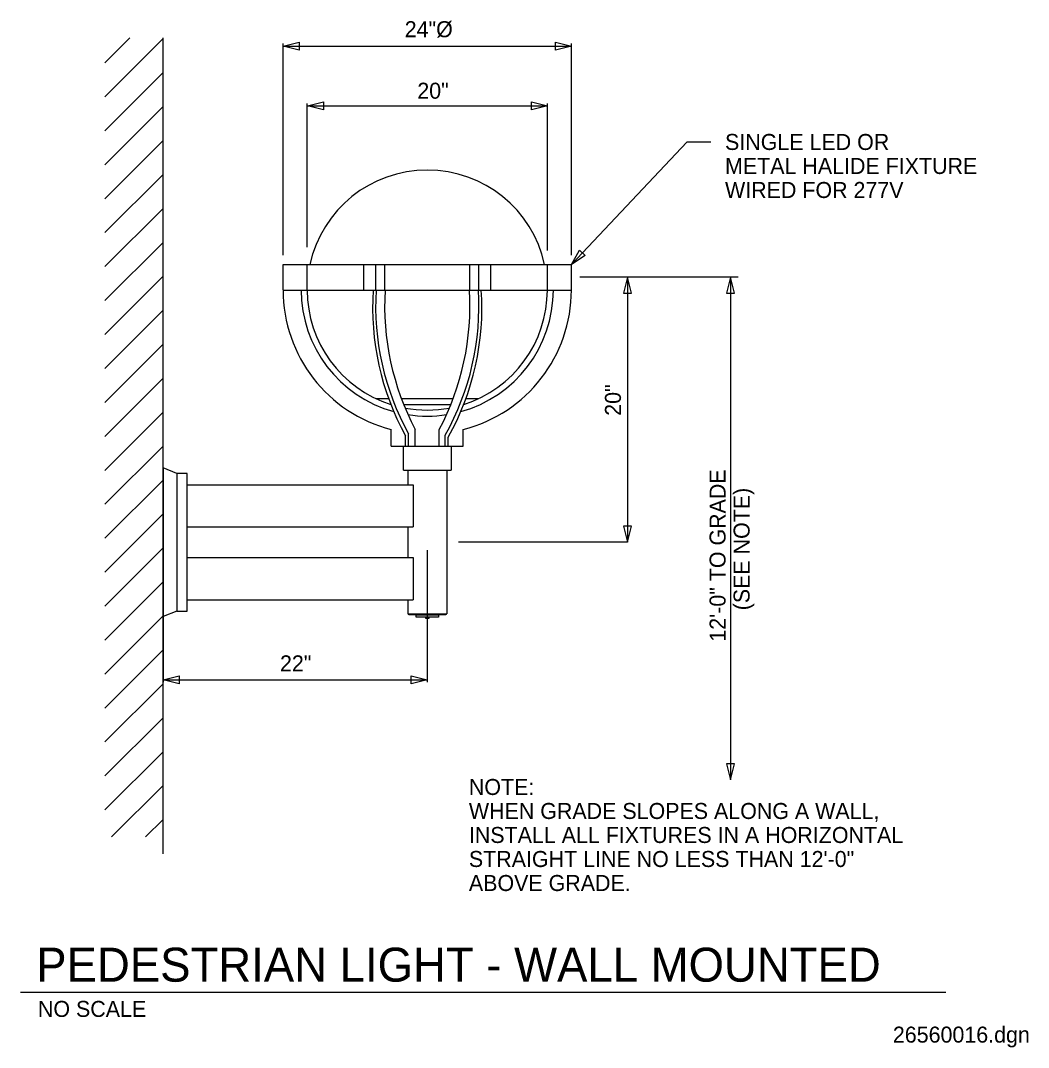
# Model space of a CAD drawing. Extents: x 10115.6 to 10157.6, y 10056 to 10098.8.
import ezdxf

# ---------------------------------------------------------------- set-up
doc = ezdxf.new("R2010")
doc.units = 0
for name, color, linetype in [('G-ANNO-TEXT', 7, 'Continuous'), ('G-DETL-LINE', 7, 'Continuous'), ('G-DETL-OTLN', 7, 'Continuous'), ('G-DETL-PATT', 7, 'Continuous')]:
    doc.layers.add(name, color=color, linetype=linetype)

msp = doc.modelspace()

# ---------------------------------------------------------------- linework, layer by layer
at = {"layer": 'G-ANNO-TEXT'}
for p, q in [((10126.542, 10089.001), (10126.542, 10097.816)), ((10138.542, 10089.001), (10138.542, 10097.816)), ((10126.542, 10097.716), (10138.542, 10097.716)), ((10127.542, 10089.333), (10127.542, 10095.321)), ((10127.556, 10095.221), (10137.542, 10095.221)), ((10137.542, 10089.204), (10137.542, 10095.321)), ((10145.489, 10088.092), (10138.897, 10088.092)), ((10140.884, 10088.092), (10140.884, 10077.048)), ((10145.161, 10088.092), (10145.161, 10067.147)), ((10140.884, 10077.048), (10133.845, 10077.048)), ((10121.542, 10076.723), (10121.542, 10071.223)), ((10132.542, 10076.723), (10132.542, 10071.223)), ((10121.542, 10071.323), (10132.542, 10071.323)), ((10115.611, 10058.314), (10154.136, 10058.314))]:
    msp.add_line(p, q, dxfattribs=at)
for points in [[(10127.209, 10097.549), (10126.542, 10097.716), (10127.209, 10097.882)], [(10137.875, 10097.882), (10138.542, 10097.716), (10137.875, 10097.549)], [(10128.223, 10095.054), (10127.556, 10095.221), (10128.223, 10095.388)], [(10136.875, 10095.388), (10137.542, 10095.221), (10136.875, 10095.054)], [(10139.12, 10088.992), (10138.542, 10088.622), (10138.878, 10089.221)], [(10141.05, 10087.426), (10140.884, 10088.092), (10140.717, 10087.426)], [(10145.328, 10087.426), (10145.161, 10088.092), (10144.995, 10087.426)], [(10140.717, 10077.715), (10140.884, 10077.048), (10141.05, 10077.715)], [(10122.209, 10071.157), (10121.542, 10071.323), (10122.209, 10071.49)], [(10131.875, 10071.49), (10132.542, 10071.323), (10131.875, 10071.157)], [(10144.995, 10067.814), (10145.161, 10067.147), (10145.328, 10067.814)]]:
    msp.add_lwpolyline(points, close=True, dxfattribs=at)
msp.add_lwpolyline([(10144.344, 10093.718), (10143.344, 10093.718), (10138.542, 10088.622)], dxfattribs=at)
at = {"layer": 'G-DETL-LINE'}
msp.add_line((10121.542, 10064.077), (10121.542, 10098.061), dxfattribs=at)
at = {"layer": 'G-DETL-OTLN'}
for p, q in [((10126.542, 10088.622), (10138.542, 10088.622)), ((10126.542, 10087.563), (10126.542, 10088.622)), ((10127.542, 10087.553), (10127.542, 10088.622)), ((10129.901, 10087.553), (10129.901, 10088.622)), ((10130.401, 10087.553), (10130.401, 10088.622)), ((10130.776, 10087.553), (10130.776, 10088.622)), ((10134.308, 10087.553), (10134.308, 10088.622)), ((10134.683, 10087.553), (10134.683, 10088.622)), ((10135.183, 10087.553), (10135.183, 10088.622)), ((10137.542, 10087.553), (10137.542, 10088.622)), ((10138.542, 10087.563), (10138.542, 10088.622)), ((10126.542, 10087.553), (10138.542, 10087.553)), ((10130.405, 10083.035), (10130.936, 10083.035)), ((10131.467, 10083.035), (10133.625, 10083.035)), ((10131.56, 10082.793), (10133.531, 10082.793)), ((10134.156, 10083.035), (10134.686, 10083.035)), ((10131.042, 10081.053), (10131.042, 10081.744)), ((10131.764, 10081.053), (10131.764, 10081.564)), ((10132.042, 10081.053), (10132.042, 10081.744)), ((10133.042, 10081.053), (10133.042, 10081.744)), ((10133.292, 10081.053), (10133.292, 10081.514)), ((10134.042, 10081.053), (10134.042, 10081.744)), ((10131.639, 10081.053), (10131.639, 10081.48)), ((10133.417, 10081.053), (10133.417, 10081.43)), ((10131.042, 10081.053), (10134.042, 10081.053)), ((10131.542, 10081.053), (10131.542, 10080.053)), ((10133.542, 10081.053), (10133.542, 10080.053)), ((10122.118, 10079.914), (10121.542, 10080.145)), ((10121.542, 10080.145), (10121.542, 10073.952)), ((10131.547, 10080.053), (10133.542, 10080.053)), ((10131.729, 10080.053), (10131.729, 10079.439)), ((10133.354, 10080.053), (10133.354, 10074.073)), ((10122.544, 10079.439), (10131.956, 10079.439)), ((10131.956, 10079.439), (10131.956, 10077.689)), ((10122.552, 10077.689), (10131.956, 10077.689)), ((10131.729, 10077.689), (10131.729, 10076.407)), ((10122.544, 10076.407), (10131.956, 10076.407)), ((10131.956, 10076.407), (10131.956, 10074.657)), ((10122.552, 10074.657), (10131.956, 10074.657)), ((10131.729, 10074.657), (10131.729, 10074.073)), ((10122.118, 10074.182), (10121.542, 10073.952)), ((10131.729, 10074.073), (10133.354, 10074.073))]:
    msp.add_line(p, q, dxfattribs=at)
for points in [[(10122.544, 10079.914), (10122.118, 10079.914), (10122.118, 10074.182), (10122.544, 10074.182)], [(10131.769, 10074.073), (10133.315, 10074.073), (10133.315, 10074.025), (10131.769, 10074.025)], [(10132.077, 10074.025), (10133.006, 10074.025), (10133.006, 10073.924), (10132.077, 10073.924)], [(10132.477, 10073.924), (10132.606, 10073.924), (10132.606, 10073.868), (10132.477, 10073.868)]]:
    msp.add_lwpolyline(points, close=True, dxfattribs=at)
for centre, radius, start, end in [((10132.542, 10087.553), 5, 12.3341, 167.6659), ((10132.542, 10087.553), 6, 180, 255.5228), ((10132.542, 10087.553), 5.25, 180, 254.576), ((10132.542, 10087.553), 5, 180, 252.3327), ((10141.282, 10086.804), 11.015, 176.0989, 208.9064), ((10141.407, 10086.889), 11.015, 176.5424, 208.9064), ((10141.782, 10086.889), 11.015, 176.5424, 207.8433), ((10123.302, 10086.889), 11.015, 332.1567, 3.4576), ((10123.677, 10086.889), 11.015, 330.7951, 3.4576), ((10123.802, 10086.804), 11.015, 330.7951, 3.9011), ((10132.542, 10087.553), 5.25, 285.4248, 0), ((10132.542, 10087.553), 6, 284.4778, 0), ((10132.542, 10087.553), 5, 287.6681, 0), ((10132.542, 10087.553), 5, 259.3669, 280.6338), ((10132.542, 10087.553), 5.25, 261.1947, 278.806)]:
    msp.add_arc(centre, radius, start, end, dxfattribs=at)
at = {"layer": 'G-DETL-PATT'}
for p, q in [((10119.117, 10097.015), (10120.164, 10098.061)), ((10119.117, 10095.6), (10121.542, 10098.025)), ((10119.117, 10094.186), (10121.542, 10096.611)), ((10119.117, 10092.772), (10121.542, 10095.197)), ((10119.117, 10091.358), (10121.542, 10093.782)), ((10119.117, 10089.944), (10121.542, 10092.368)), ((10119.117, 10088.529), (10121.542, 10090.954)), ((10119.117, 10087.115), (10121.542, 10089.54)), ((10119.117, 10085.701), (10121.542, 10088.125)), ((10119.117, 10084.287), (10121.542, 10086.711)), ((10119.117, 10082.873), (10121.542, 10085.297)), ((10119.117, 10081.458), (10121.542, 10083.883)), ((10119.117, 10080.044), (10121.542, 10082.469)), ((10119.117, 10078.63), (10121.542, 10081.054)), ((10119.117, 10077.216), (10121.542, 10079.64)), ((10119.117, 10075.802), (10121.542, 10078.226)), ((10119.117, 10074.387), (10121.542, 10076.812)), ((10119.117, 10072.973), (10121.542, 10075.398)), ((10119.117, 10071.559), (10121.542, 10073.983)), ((10119.117, 10070.145), (10121.542, 10072.569)), ((10119.117, 10068.73), (10121.542, 10071.155)), ((10119.117, 10067.316), (10121.542, 10069.741)), ((10119.117, 10065.902), (10121.542, 10068.326)), ((10119.403, 10064.773), (10121.542, 10066.912)), ((10120.817, 10064.773), (10121.542, 10065.498))]:
    msp.add_line(p, q, dxfattribs=at)

# ---------------------------------------------------------------- texts
at = {"layer": 'G-ANNO-TEXT'}
for s, height, p in [('24"Ø ', 0.6667, (10131.603, 10098.085)), ('20"', 0.6667, (10132.127, 10095.523)), ('SINGLE LED OR', 0.66667, (10144.937, 10093.388)), ('METAL HALIDE FIXTURE', 0.66667, (10144.937, 10092.388)), ('WIRED FOR 277V', 0.66667, (10144.937, 10091.388)), ('22"', 0.6667, (10126.411, 10071.671)), ('NOTE:', 0.6667, (10134.274, 10066.523)), ('WHEN GRADE SLOPES ALONG A WALL,', 0.66667, (10134.274, 10065.523)), ('INSTALL ALL FIXTURES IN A HORIZONTAL', 0.66667, (10134.274, 10064.523)), ('STRAIGHT LINE NO LESS THAN 12\'-0"', 0.66667, (10134.274, 10063.523)), ('ABOVE GRADE.', 0.66667, (10134.274, 10062.523)), ('PEDESTRIAN LIGHT - WALL MOUNTED', 1.41667, (10116.263, 10058.746)), ('NO SCALE', 0.6667, (10116.334, 10057.279)), ('26560016.dgn', 0.66667, (10151.925, 10056.208))]:
    msp.add_text(s, height=height, dxfattribs=at).set_placement(p)
for s, height, p in [('20"', 0.6667, (10140.605, 10082.317)), ('12\'-0" TO GRADE', 0.66667, (10144.961, 10072.908)), ('(SEE NOTE)', 0.6667, (10145.961, 10074.215))]:
    msp.add_text(s, height=height, rotation=90, dxfattribs=at).set_placement(p)

doc.saveas('drawing.dxf')
